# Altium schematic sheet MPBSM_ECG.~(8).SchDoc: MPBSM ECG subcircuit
size 431 x 279 mm; Date: Not shown in title block; ApprovedBy: Not shown in title block; CheckedBy: Not shown in title block; Author: Not shown in title block; CompanyName: Not shown in title block; Engineer: Not shown in title block; Organization: Not shown in title block; Address1: Not shown in title block; Address2: Not shown in title block; Address3: Not shown in title block; Address4: Not shown in title block; DocumentNumber: 8; Revision: Use project parameter SCH_Rev; SheetNumber: 7; SheetTotal: 12; PageSetup: Record=PageOptions¦CenterHorizontal=True¦CenterVertical=True¦PrintScale=1.00¦XCorrection=1.00¦YCorrection=1.00¦PrintKind=0¦BorderSize=5000000¦LeftOffset=0¦BottomOffset=0¦Orientation=2¦PaperLength=1000¦PaperWidth=1000¦Scale=100¦PaperSource=15¦PrintQuality=600¦MediaType=1¦DitherType=10¦PaperKind=Letter¦PrintScaleMode=1
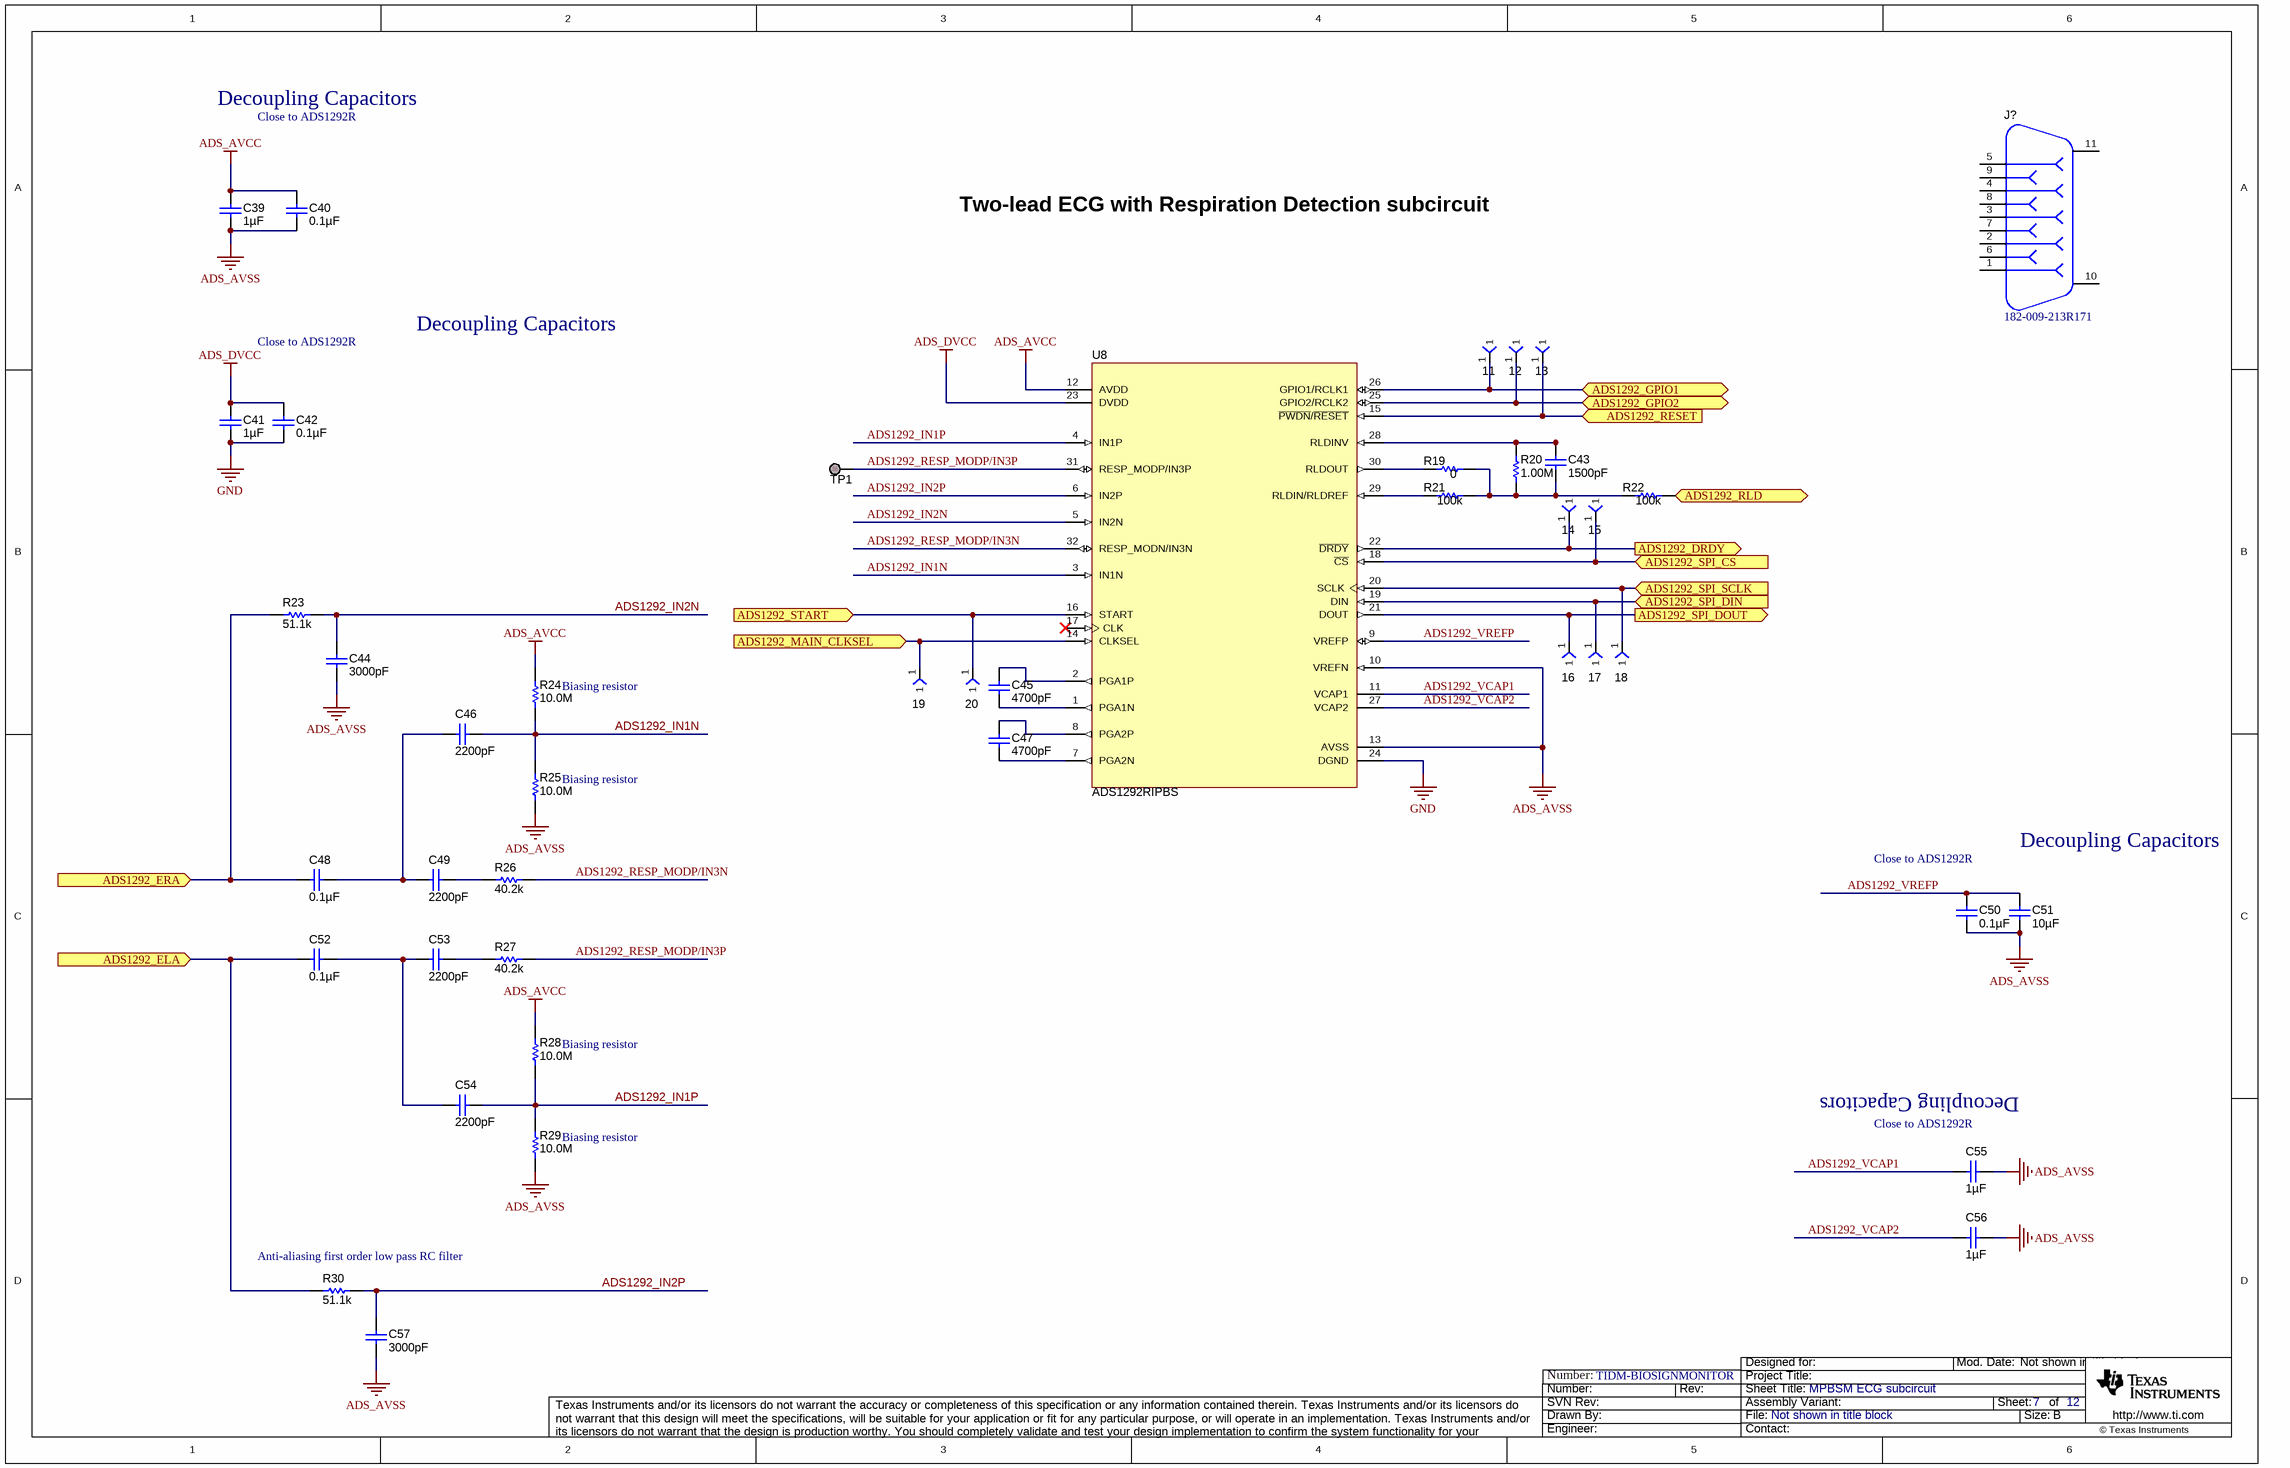
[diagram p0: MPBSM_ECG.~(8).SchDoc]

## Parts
11  TP-025-SMT  [TP_25MIL-SMT]  (value not drawn)
12  TP-025-SMT  [TP_25MIL-SMT]  (value not drawn)
13  TP-025-SMT  [TP_25MIL-SMT]  (value not drawn)
14  TP-025-SMT  [TP_25MIL-SMT]  (value not drawn)
15  TP-025-SMT  [TP_25MIL-SMT]  (value not drawn)
16  TP-025-SMT  [TP_25MIL-SMT]  (value not drawn)
17  TP-025-SMT  [TP_25MIL-SMT]  (value not drawn)
18  TP-025-SMT  [TP_25MIL-SMT]  (value not drawn)
19  TP-025-SMT  [TP_25MIL-SMT]  (value not drawn)
20  TP-025-SMT  [TP_25MIL-SMT]  (value not drawn)
C39  ValueDisplayed: 1µF  [0402]  (hidden comment: C1005X5R1C105K050BC)
C40  ValueDisplayed: 0.1µF  [0402]  (hidden comment: C1005X5R1A104K)
C41  ValueDisplayed: 1µF  [0402]  (hidden comment: C1005X5R1C105K050BC)
C42  ValueDisplayed: 0.1µF  [0402]  (hidden comment: C1005X5R1A104K)
C43  ValueDisplayed: 1500pF  [0603]  (hidden comment: C0603C152K5RACTU)
C44  ValueDisplayed: 3000pF  [0603]  (hidden comment: GRM1885C1H302JA01D)
C45  ValueDisplayed: 4700pF  [0402]  (hidden comment: GRM155R61A472KA01D)
C46  ValueDisplayed: 2200pF  [0402]  (hidden comment: C1005X8R1H222K)
C47  ValueDisplayed: 4700pF  [0402]  (hidden comment: GRM155R61A472KA01D)
C48  ValueDisplayed: 0.1µF  [0402]  (hidden comment: C1005X5R1A104K)
C49  ValueDisplayed: 2200pF  [0402]  (hidden comment: C1005X8R1H222K)
C50  ValueDisplayed: 0.1µF  [0402]  (hidden comment: C1005X5R1A104K)
C51  ValueDisplayed: 10µF  [0603]  (hidden comment: C1608X5R0J106M)
C52  ValueDisplayed: 0.1µF  [0402]  (hidden comment: C1005X5R1A104K)
C53  ValueDisplayed: 2200pF  [0402]  (hidden comment: C1005X8R1H222K)
C54  ValueDisplayed: 2200pF  [0402]  (hidden comment: C1005X8R1H222K)
C55  ValueDisplayed: 1µF  [0402]  (hidden comment: C1005X5R1C105K050BC)
C56  ValueDisplayed: 1µF  [0402]  (hidden comment: C1005X5R1C105K050BC)
C57  ValueDisplayed: 3000pF  [0603]  (hidden comment: GRM1885C1H302JA01D)
J?  182-009-213R171  [NORCOMP_182-009-213R171]
R19  ValueDisplayed: 0  [0402]  (hidden comment: ERJ-2GE0R00X)
R20  ValueDisplayed: 1.00M  [0402]  (hidden comment: ERJ-2RKF1004X)
R21  ValueDisplayed: 100k  [0402]  (hidden comment: ERJ-2RKF1003X)
R22  ValueDisplayed: 100k  [0402]  (hidden comment: ERJ-2RKF1003X)
R23  ValueDisplayed: 51.1k  [0402]  (hidden comment: CRCW040251K1FKED)
R24  ValueDisplayed: 10.0M  [0402]  (hidden comment: CRCW040210M0FKED)
R25  ValueDisplayed: 10.0M  [0402]  (hidden comment: CRCW040210M0FKED)
R26  ValueDisplayed: 40.2k  [0402]  (hidden comment: CRCW040240K2FKED)
R27  ValueDisplayed: 40.2k  [0402]  (hidden comment: CRCW040240K2FKED)
R28  ValueDisplayed: 10.0M  [0402]  (hidden comment: CRCW040210M0FKED)
R29  ValueDisplayed: 10.0M  [0402]  (hidden comment: CRCW040210M0FKED)
R30  ValueDisplayed: 51.1k  [0402]  (hidden comment: CRCW040251K1FKED)
TP1  Pogo Pad  [PogoPad]  (value not drawn)  (no BOM)
U8  ADS1292RIPBS  [PBS0032A_N]

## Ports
ADS1292_DRDY (out), ADS1292_ELA (in), ADS1292_ERA (in), ADS1292_GPIO1 (bidir), ADS1292_GPIO2 (bidir), ADS1292_MAIN_CLKSEL (in), ADS1292_RESET (in), ADS1292_RLD (out), ADS1292_SPI_CS (in), ADS1292_SPI_DIN (in), ADS1292_SPI_DOUT (out), ADS1292_SPI_SCLK (in), ADS1292_START (in)

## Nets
ADS_AVCC: C39.1 C40.1 R24.2 R28.2 U8.12(AVDD)
ADS_AVSS: C39.2 C40.2 C44.2 C50.2 C51.2 C55.2 C56.2 C57.2 R25.1 R29.1 U8.10(VREFN) U8.13(AVSS)
ADS_DVCC: C41.1 C42.1 U8.23(DVDD)
GND: C41.2 C42.2 U8.24(DGND)
ADS1292_DRDY: 14.1 U8.22(~{DRDY}) ; port ADS1292_DRDY
ADS1292_ELA: C52.1 R30.1 ; port ADS1292_ELA
ADS1292_ERA: C48.1 R23.1 ; port ADS1292_ERA
ADS1292_GPIO1: 11.1 U8.26(GPIO1/RCLK1) ; port ADS1292_GPIO1
ADS1292_GPIO2: 12.1 U8.25(GPIO2/RCLK2) ; port ADS1292_GPIO2
ADS1292_IN1N: C46.1 R24.1 R25.2 U8.3(IN1N)
ADS1292_IN1P: C54.1 R28.1 R29.2 U8.4(IN1P)
ADS1292_IN2N: C44.1 R23.2 U8.5(IN2N)
ADS1292_IN2P: C57.1 R30.2 U8.6(IN2P)
ADS1292_MAIN_CLKSEL: 19.1 U8.14(CLKSEL) ; port ADS1292_MAIN_CLKSEL
ADS1292_RESET: 13.1 U8.15(~{PWDN}/~{RESET}) ; port ADS1292_RESET
ADS1292_RESP_MODP/IN3N: R26.2 U8.32(RESP_MODN/IN3N)
ADS1292_RESP_MODP/IN3P: R27.2 TP1.1 U8.31(RESP_MODP/IN3P)
ADS1292_RLD: R22.2 ; port ADS1292_RLD
ADS1292_SPI_CS: 15.1 U8.18(~{CS}) ; port ADS1292_SPI_CS
ADS1292_SPI_DIN: 17.1 U8.19(DIN) ; port ADS1292_SPI_DIN
ADS1292_SPI_DOUT: 16.1 U8.21(DOUT) ; port ADS1292_SPI_DOUT
ADS1292_SPI_SCLK: 18.1 U8.20(SCLK) ; port ADS1292_SPI_SCLK
ADS1292_START: 20.1 U8.16(START) ; port ADS1292_START
ADS1292_VCAP1: C55.1 U8.11(VCAP1)
ADS1292_VCAP2: C56.1 U8.27(VCAP2)
ADS1292_VREFP: C50.1 C51.1 U8.9(VREFP)
NetC43_1: C43.1 R19.2 R20.2 R21.2 R22.1
NetC43_2: C43.2 R20.1 U8.28(RLDINV)
NetC45_1: C45.1 U8.2(PGA1P)
NetC45_2: C45.2 U8.1(PGA1N)
NetC46_2: C46.2 C48.2 C49.2
NetC47_1: C47.1 U8.8(PGA2P)
NetC47_2: C47.2 U8.7(PGA2N)
NetC49_1: C49.1 R26.1
NetC52_2: C52.2 C53.2 C54.2
NetC53_1: C53.1 R27.1
NetR19_1: R19.1 U8.30(RLDOUT)
NetR21_1: R21.1 U8.29(RLDIN/RLDREF)

Not connected (* = marked no-connect by the designer): J? 1 2 3 4 5 6 7 8 9 10 11; U8 17(CLK)*

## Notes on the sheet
- Decoupling Capacitors
- Close to ADS1292R
- Two-lead ECG with Respiration Detection subcircuit
- (near R24) Biasing resistor
- (near R25) Biasing resistor
- (near R28) Biasing resistor
- (near R29) Biasing resistor
- (near C55) Close to ADS1292R
- (near R30) Anti-aliasing first order low pass RC filter
- Number:
- TIDM-BIOSIGNMONITOR

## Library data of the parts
11-20 = TP-025-SMT: Test Point, O.025"; Manufacturer: STD; Value: STD
C39 C41 C55 C56 = C1005X5R1C105K050BC: CAP, CERM, 1 µF, 16 V, +/- 10%, X5R, 0402; Manufacturer: TDK; Polarized: N; CompType: Capacitor; Value: 1uF; U/M: EA; Cap_F: 0.000001; Tolerance_%: 10; Value1: Unknown; VDC_V: 16; Value2: 16V; TaMin_C: -55; TaMax_C: 85
C40 C42 C48 C50 C52 = C1005X5R1A104K: CAP, CERM, 0.1 µF, 10 V, +/- 10%, X5R, 0402; Manufacturer: TDK; Polarized: N; CompType: Capacitor; Value: 0.1uF; U/M: EA; Cap_F: 0.0000001; Tolerance_%: 10; ESR_ohm: 0.0186; Value1: 0.0186 ohm; Value2: 10V; TaMin_C: -55; TaMax_C: 85
C43 = C0603C152K5RACTU: CAP, CERM, 1500 pF, 50 V, +/- 10%, X7R, 0603; Manufacturer: Kemet; Polarized: N; CompType: Capacitor; Value: 1500pF; U/M: EA; Cap_F: 0.0000000015; Tolerance_%: 10; Value1: Unknown; VDC_V: 50; Value2: 50V; TaMin_C: -55; TaMax_C: 125
C44 C57 = GRM1885C1H302JA01D: CAP, CERM, 3000 pF, 50 V, +/- 5%, C0G/NP0, 0603; Manufacturer: MuRata; Polarized: N; CompType: Capacitor; Value: 3000pF; U/M: EA; Cap_F: 0.000000003; Tolerance_%: 5; Value1: Unknown; VDC_V: 50; Value2: 50V; TaMin_C: -55; TaMax_C: 125
C45 C47 = GRM155R61A472KA01D: CAP, CERM, 4700 pF, 10 V, +/- 10%, X5R, 0402; Manufacturer: MuRata; Polarized: N; CompType: Capacitor; Value: 4700pF; U/M: EA; Cap_F: 0.0000000047; Tolerance_%: 10; Value1: Unknown; Value2: 10V; TaMin_C: -55; TaMax_C: 85
C46 C49 C53 C54 = C1005X8R1H222K: CAP, CERM, 2200 pF, 50 V, +/- 10%, X8R, 0402; Manufacturer: TDK; Polarized: N; CompType: Capacitor; Value: 2200pF; U/M: EA; Cap_F: 0.0000000022; Tolerance_%: 10; ESR_ohm: 0.1736; Value1: 0.1736 ohm; VDC_V: 50; Value2: 50V; TaMin_C: -55; TaMax_C: 150
C51 = C1608X5R0J106M: CAP, CERM, 10 µF, 6.3 V, +/- 20%, X5R, 0603; Manufacturer: TDK; Polarized: N; CompType: Capacitor; Value: 10uF; U/M: EA; Cap_F: 0.00001; Tolerance_%: 20; ESR_ohm: 0.005; Value1: 0.005 ohm; VDC_V: 6.3; Value2: 6.3V; IRMS_A: 1.9; TaMin_C: -25; TaMax_C: 85
J? = 182-009-213R171: CONN DB9 FEMALE R/A SOLDER TH; Manufacturer: NorComp; SymbolCreator: a0412235; CompType: Connector
R19 = ERJ-2GE0R00X: RES, 0, 5%, 0.063 W, 0402; Manufacturer: Panasonic; CompType: Resistor; Value: 0; Value_Code: 0000; Tolerance_%: 5; Power_W: 0.063; Value2: 0.063W; VDC_V: 50; TempCo: 600 ppm/C; EIA_Code: E24; U/M: EA
R20 = ERJ-2RKF1004X: RES, 1.00 M, 1%, 0.1 W, 0402; Manufacturer: Panasonic; CompType: Resistor; Value: 1.00Meg; Res_ohm: 1000000; Value_Code: 1M00; Tolerance_%: 1; Power_W: 0.1; Value2: 0.1W; VDC_V: 50; TempCo: 100 ppm/C; EIA_Code: E96; U/M: EA
R21 R22 = ERJ-2RKF1003X: RES, 100 k, 1%, 0.1 W, 0402; Manufacturer: Panasonic; CompType: Resistor; Value: 100k; Res_ohm: 100000; Tolerance_%: 1; Power_W: 0.1; Value2: 0.1W; VDC_V: 50; TempCo: 100 ppm/C; EIA_Code: E96; U/M: EA
R23 R30 = CRCW040251K1FKED: RES, 51.1 k, 1%, 0.063 W, 0402; Manufacturer: Vishay-Dale; CompType: Resistor; Value: 51.1k; Res_ohm: 51100; Value_Code: 51k1; Tolerance_%: 1; Power_W: 0.063; Value2: 0.063W; VDC_V: 50; TempCo: 100 ppm/C; EIA_Code: E96; U/M: EA
R24 R25 R28 R29 = CRCW040210M0FKED: RES, 10.0 M, 1%, 0.063 W, 0402; Manufacturer: Vishay-Dale; CompType: Resistor; Value: 10.0Meg; Res_ohm: 10000000; Value_Code: 10M0; Tolerance_%: 1; Power_W: 0.063; Value2: 0.063W; VDC_V: 50; TempCo: 100 ppm/C; EIA_Code: E96; U/M: EA
R26 R27 = CRCW040240K2FKED: RES, 40.2 k, 1%, 0.063 W, 0402; Manufacturer: Vishay-Dale; CompType: Resistor; Value: 40.2k; Res_ohm: 40200; Value_Code: 40k2; Tolerance_%: 1; Power_W: 0.063; Value2: 0.063W; VDC_V: 50; TempCo: 100 ppm/C; EIA_Code: E96; U/M: EA
TP1 = PogoPad: Pad for Pogo Pin Connector; SymbolCreator: codlsc
U8 = ADS1292RIPBS: Low-Power, 2-Channel, 24-Bit Analog Front-End for Biopotential Measurement, PBS0032A; Alternate Manufacturer: None; Manufacturer: Texas Instruments; SymbolCreator: Altium; CompType: IC; U/M: EA; SupplyCurrent: 740µW; SupplyVoltageAnalog: 2.7 V ~ 5.25 V; SupplyVoltageAnalogMax_V: 5.25 V; SupplyVoltageAnalogMin_V: 2.7 V; TaMax_C: + 85 °C; TaMin_C: -40 °C; Value: Mixed-Signal; Value1: Not Applicable; SupplyVoltageDigitalMax_V: 3.6 V; SupplyVoltageDigital: 1.7 V ~ 3.6 V; SupplyVoltageDigitalMin_V: 1.7 V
